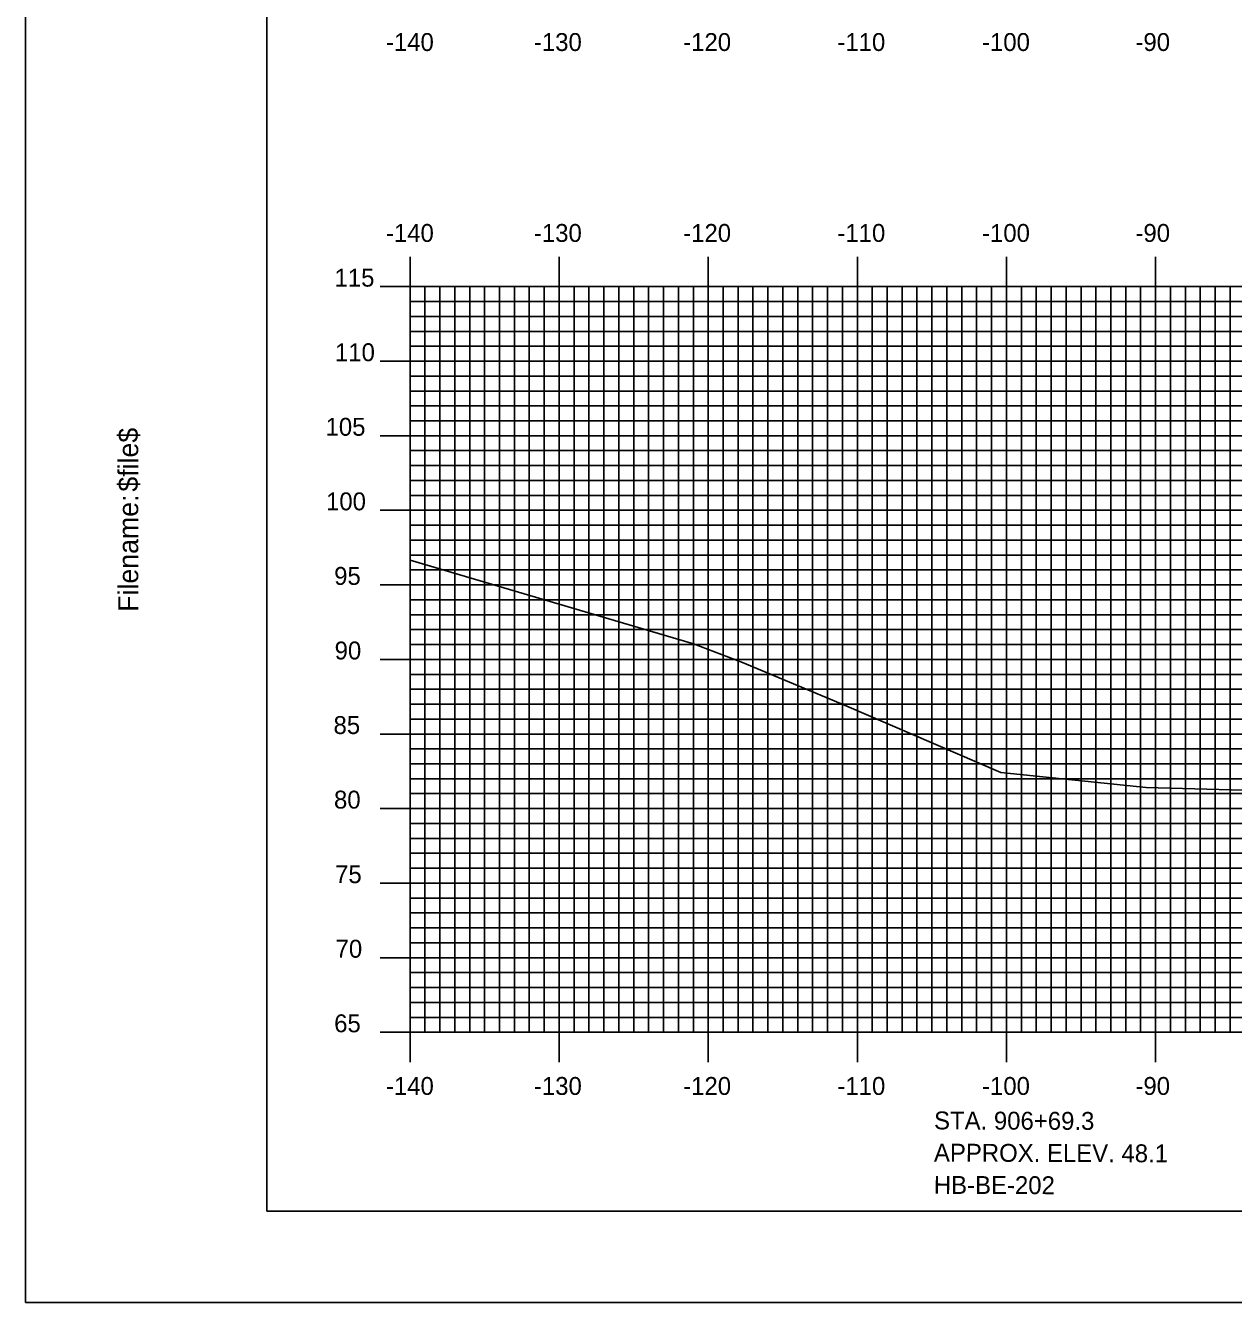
# Model space of a CAD drawing. Extents: x 857897 to 858240, y 364765 to 364985.
# Drawn here: x 857897 to 857978, y 364765.2 to 364850.8 of the extents above; entities that cross this region are included whole.
import ezdxf

# ---------------------------------------------------------------- set-up
doc = ezdxf.new("R2010")
doc.units = 0
for name, color, linetype in [('BORDER', 7, 'Continuous'), ('BORING - REFUSAL', 7, 'Continuous'), ('H_V ANNOTATION', 7, 'Continuous'), ('MAJOR', 7, 'Continuous'), ('MINOR', 7, 'Continuous'), ('PLOT BOUNDARY', 7, 'Continuous'), ('S_Roadway_Centerline', 7, 'Continuous')]:
    doc.layers.add(name, color=color, linetype=linetype)

msp = doc.modelspace()

# ---------------------------------------------------------------- linework, layer by layer
at = {"layer": 'BORDER'}
msp.add_lwpolyline([(857913.221, 364771.302), (858233.221, 364771.302), (858233.221, 364981.302), (857913.221, 364981.302)], close=True, dxfattribs=at)
at = {"layer": 'MAJOR'}
for p, q in [((857922.821, 364835.306), (857922.821, 364833.302)), ((857932.821, 364835.306), (857932.821, 364833.302)), ((857942.821, 364835.306), (857942.821, 364833.302)), ((857952.821, 364835.306), (857952.821, 364833.302)), ((857962.821, 364835.306), (857962.821, 364833.302)), ((857972.821, 364835.306), (857972.821, 364833.302)), ((857920.817, 364833.302), (857922.821, 364833.302)), ((857922.821, 364833.302), (858202.821, 364833.302)), ((857922.821, 364783.302), (857922.821, 364833.302)), ((857922.821, 364783.302), (857922.821, 364833.302)), ((857922.821, 364833.302), (858202.821, 364833.302)), ((857932.821, 364783.302), (857932.821, 364833.302)), ((857942.821, 364783.302), (857942.821, 364833.302)), ((857952.821, 364783.302), (857952.821, 364833.302)), ((857962.821, 364783.302), (857962.821, 364833.302)), ((857972.821, 364783.302), (857972.821, 364833.302)), ((857920.817, 364828.302), (857922.821, 364828.302)), ((857922.821, 364828.302), (858202.821, 364828.302)), ((857920.817, 364823.302), (857922.821, 364823.302)), ((857922.821, 364823.302), (858202.821, 364823.302)), ((857920.817, 364818.302), (857922.821, 364818.302)), ((857922.821, 364818.302), (858202.821, 364818.302)), ((857920.817, 364813.302), (857922.821, 364813.302)), ((857922.821, 364813.302), (858202.821, 364813.302)), ((857920.817, 364808.302), (857922.821, 364808.302)), ((857922.821, 364808.302), (858202.821, 364808.302)), ((857920.817, 364803.302), (857922.821, 364803.302)), ((857922.821, 364803.302), (858202.821, 364803.302)), ((857920.817, 364798.302), (857922.821, 364798.302)), ((857922.821, 364798.302), (858202.821, 364798.302)), ((857920.817, 364793.302), (857922.821, 364793.302)), ((857922.821, 364793.302), (858202.821, 364793.302)), ((857920.817, 364788.302), (857922.821, 364788.302)), ((857922.821, 364788.302), (858202.821, 364788.302)), ((857920.817, 364783.302), (857922.821, 364783.302)), ((857922.821, 364783.302), (858202.821, 364783.302)), ((857922.821, 364783.302), (858202.821, 364783.302)), ((857922.821, 364781.298), (857922.821, 364783.302)), ((857932.821, 364781.298), (857932.821, 364783.302)), ((857942.821, 364781.298), (857942.821, 364783.302)), ((857952.821, 364781.298), (857952.821, 364783.302)), ((857962.821, 364781.298), (857962.821, 364783.302)), ((857972.821, 364781.298), (857972.821, 364783.302))]:
    msp.add_line(p, q, dxfattribs=at)
at = {"layer": 'MINOR'}
for p, q in [((857923.821, 364783.302), (857923.821, 364833.302)), ((857924.821, 364783.302), (857924.821, 364833.302)), ((857925.821, 364783.302), (857925.821, 364833.302)), ((857926.821, 364783.302), (857926.821, 364833.302)), ((857927.821, 364783.302), (857927.821, 364833.302)), ((857928.821, 364783.302), (857928.821, 364833.302)), ((857929.821, 364783.302), (857929.821, 364833.302)), ((857930.821, 364783.302), (857930.821, 364833.302)), ((857931.821, 364783.302), (857931.821, 364833.302)), ((857933.821, 364783.302), (857933.821, 364833.302)), ((857934.821, 364783.302), (857934.821, 364833.302)), ((857935.821, 364783.302), (857935.821, 364833.302)), ((857936.821, 364783.302), (857936.821, 364833.302)), ((857937.821, 364783.302), (857937.821, 364833.302)), ((857938.821, 364783.302), (857938.821, 364833.302)), ((857939.821, 364783.302), (857939.821, 364833.302)), ((857940.821, 364783.302), (857940.821, 364833.302)), ((857941.821, 364783.302), (857941.821, 364833.302)), ((857943.821, 364783.302), (857943.821, 364833.302)), ((857944.821, 364783.302), (857944.821, 364833.302)), ((857945.821, 364783.302), (857945.821, 364833.302)), ((857946.821, 364783.302), (857946.821, 364833.302)), ((857947.821, 364783.302), (857947.821, 364833.302)), ((857948.821, 364783.302), (857948.821, 364833.302)), ((857949.821, 364783.302), (857949.821, 364833.302)), ((857950.821, 364783.302), (857950.821, 364833.302)), ((857951.821, 364783.302), (857951.821, 364833.302)), ((857953.821, 364783.302), (857953.821, 364833.302)), ((857954.821, 364783.302), (857954.821, 364833.302)), ((857955.821, 364783.302), (857955.821, 364833.302)), ((857956.821, 364783.302), (857956.821, 364833.302)), ((857957.821, 364783.302), (857957.821, 364833.302)), ((857958.821, 364783.302), (857958.821, 364833.302)), ((857959.821, 364783.302), (857959.821, 364833.302)), ((857960.821, 364783.302), (857960.821, 364833.302)), ((857961.821, 364783.302), (857961.821, 364833.302)), ((857963.821, 364783.302), (857963.821, 364833.302)), ((857964.821, 364783.302), (857964.821, 364833.302)), ((857965.821, 364783.302), (857965.821, 364833.302)), ((857966.821, 364783.302), (857966.821, 364833.302)), ((857967.821, 364783.302), (857967.821, 364833.302)), ((857968.821, 364783.302), (857968.821, 364833.302)), ((857969.821, 364783.302), (857969.821, 364833.302)), ((857970.821, 364783.302), (857970.821, 364833.302)), ((857971.821, 364783.302), (857971.821, 364833.302)), ((857973.821, 364783.302), (857973.821, 364833.302)), ((857974.821, 364783.302), (857974.821, 364833.302)), ((857975.821, 364783.302), (857975.821, 364833.302)), ((857976.821, 364783.302), (857976.821, 364833.302)), ((857977.821, 364783.302), (857977.821, 364833.302)), ((857922.821, 364832.302), (858202.821, 364832.302)), ((857922.821, 364832.302), (857924.825, 364832.302)), ((857922.821, 364831.302), (858202.821, 364831.302)), ((857922.821, 364831.302), (857924.825, 364831.302)), ((857922.821, 364830.302), (858202.821, 364830.302)), ((857922.821, 364830.302), (857924.825, 364830.302)), ((857922.821, 364829.302), (858202.821, 364829.302)), ((857922.821, 364829.302), (857924.825, 364829.302)), ((857922.821, 364827.302), (858202.821, 364827.302)), ((857922.821, 364827.302), (857924.825, 364827.302)), ((857922.821, 364826.302), (858202.821, 364826.302)), ((857922.821, 364826.302), (857924.825, 364826.302)), ((857922.821, 364825.302), (858202.821, 364825.302)), ((857922.821, 364825.302), (857924.825, 364825.302)), ((857922.821, 364824.302), (858202.821, 364824.302)), ((857922.821, 364824.302), (857924.825, 364824.302)), ((857922.821, 364822.302), (858202.821, 364822.302)), ((857922.821, 364822.302), (857924.825, 364822.302)), ((857922.821, 364821.302), (858202.821, 364821.302)), ((857922.821, 364821.302), (857924.825, 364821.302)), ((857922.821, 364820.302), (858202.821, 364820.302)), ((857922.821, 364820.302), (857924.825, 364820.302)), ((857922.821, 364819.302), (858202.821, 364819.302)), ((857922.821, 364819.302), (857924.825, 364819.302)), ((857922.821, 364817.302), (858202.821, 364817.302)), ((857922.821, 364817.302), (857924.825, 364817.302)), ((857922.821, 364816.302), (858202.821, 364816.302)), ((857922.821, 364816.302), (857924.825, 364816.302)), ((857922.821, 364815.302), (858202.821, 364815.302)), ((857922.821, 364815.302), (857924.825, 364815.302)), ((857922.821, 364814.302), (858202.821, 364814.302)), ((857922.821, 364814.302), (857924.825, 364814.302)), ((857922.821, 364812.302), (858202.821, 364812.302)), ((857922.821, 364812.302), (857924.825, 364812.302)), ((857922.821, 364811.302), (858202.821, 364811.302)), ((857922.821, 364811.302), (857924.825, 364811.302)), ((857922.821, 364810.302), (858202.821, 364810.302)), ((857922.821, 364810.302), (857924.825, 364810.302)), ((857922.821, 364809.302), (858202.821, 364809.302)), ((857922.821, 364809.302), (857924.825, 364809.302)), ((857922.821, 364807.302), (858202.821, 364807.302)), ((857922.821, 364807.302), (857924.825, 364807.302)), ((857922.821, 364806.302), (858202.821, 364806.302)), ((857922.821, 364806.302), (857924.825, 364806.302)), ((857922.821, 364805.302), (858202.821, 364805.302)), ((857922.821, 364805.302), (857924.825, 364805.302)), ((857922.821, 364804.302), (858202.821, 364804.302)), ((857922.821, 364804.302), (857924.825, 364804.302)), ((857922.821, 364802.302), (858202.821, 364802.302)), ((857922.821, 364802.302), (857924.825, 364802.302)), ((857922.821, 364801.302), (858202.821, 364801.302)), ((857922.821, 364801.302), (857924.825, 364801.302)), ((857922.821, 364800.302), (858202.821, 364800.302)), ((857922.821, 364800.302), (857924.825, 364800.302)), ((857922.821, 364799.302), (858202.821, 364799.302)), ((857922.821, 364799.302), (857924.825, 364799.302)), ((857922.821, 364797.302), (858202.821, 364797.302)), ((857922.821, 364797.302), (857924.825, 364797.302)), ((857922.821, 364796.302), (858202.821, 364796.302)), ((857922.821, 364796.302), (857924.825, 364796.302)), ((857922.821, 364795.302), (858202.821, 364795.302)), ((857922.821, 364795.302), (857924.825, 364795.302)), ((857922.821, 364794.302), (858202.821, 364794.302)), ((857922.821, 364794.302), (857924.825, 364794.302)), ((857922.821, 364792.302), (858202.821, 364792.302)), ((857922.821, 364792.302), (857924.825, 364792.302)), ((857922.821, 364791.302), (858202.821, 364791.302)), ((857922.821, 364791.302), (857924.825, 364791.302)), ((857922.821, 364790.302), (858202.821, 364790.302)), ((857922.821, 364790.302), (857924.825, 364790.302)), ((857922.821, 364789.302), (858202.821, 364789.302)), ((857922.821, 364789.302), (857924.825, 364789.302)), ((857922.821, 364787.302), (858202.821, 364787.302)), ((857922.821, 364787.302), (857924.825, 364787.302)), ((857922.821, 364786.302), (858202.821, 364786.302)), ((857922.821, 364786.302), (857924.825, 364786.302)), ((857922.821, 364785.302), (858202.821, 364785.302)), ((857922.821, 364785.302), (857924.825, 364785.302)), ((857922.821, 364784.302), (858202.821, 364784.302)), ((857922.821, 364784.302), (857924.825, 364784.302))]:
    msp.add_line(p, q, dxfattribs=at)
at = {"layer": 'PLOT BOUNDARY'}
msp.add_lwpolyline([(857897.034, 364765.184), (858237.034, 364765.184), (858237.034, 364985.184), (857897.034, 364985.184)], close=True, dxfattribs=at)
at = {"layer": 'S_Roadway_Centerline'}
msp.add_lwpolyline([(857922.821, 364814.97), (857941.825, 364809.359), (857945.12, 364808.108), (857951.954, 364805.245), (857962.433, 364800.714), (857972.196, 364799.708), (857991.726, 364799.171), (857996.315, 364799.061), (858003.846, 364798.865), (858013.027, 364798.718), (858019.735, 364798.597), (858026.217, 364798.531), (858028.554, 364798.624), (858052.488, 364799.533), (858057.96, 364799.363), (858073.459, 364798.606), (858081.082, 364798.117)], dxfattribs=at)

# ---------------------------------------------------------------- texts
at = {"layer": 'BORDER'}
for s, p in [('$file$', (857904.591, 364819.553)), ('Filename:', (857904.591, 364811.499))]:
    msp.add_text(s, height=1.3392, rotation=90, dxfattribs=at).set_placement(p)
at = {"layer": 'BORING - REFUSAL'}
for s, p in [('STA. 906+69.3', (857957.964, 364776.79)), ('APPROX. ELEV. 48.1', (857957.957, 364774.63)), ('HB-BE-202', (857957.95, 364772.47))]:
    msp.add_text(s, height=1.2, rotation=359.81416, dxfattribs=at).set_placement(p)
at = {"layer": 'H_V ANNOTATION'}
for s, p in [('-140', (857921.205, 364849.102)), ('-130', (857931.13, 364849.102)), ('-120', (857941.14, 364849.102)), ('-110', (857951.483, 364849.102)), ('-100', (857961.183, 364849.102)), ('-90', (857971.472, 364849.102)), ('-140', (857921.205, 364836.302)), ('-130', (857931.13, 364836.302)), ('-120', (857941.14, 364836.302)), ('-110', (857951.483, 364836.302)), ('-100', (857961.183, 364836.302)), ('-90', (857971.472, 364836.302)), ('115', (857917.755, 364833.302)), ('110', (857917.787, 364828.302)), ('105', (857917.155, 364823.302)), ('100', (857917.187, 364818.302)), ('95', (857917.733, 364813.302)), ('90', (857917.765, 364808.302)), ('85', (857917.69, 364803.302)), ('80', (857917.722, 364798.302)), ('75', (857917.797, 364793.302)), ('70', (857917.829, 364788.302)), ('65', (857917.733, 364783.302)), ('-140', (857921.205, 364779.102)), ('-130', (857931.13, 364779.102)), ('-120', (857941.14, 364779.102)), ('-110', (857951.483, 364779.102)), ('-100', (857961.183, 364779.102)), ('-90', (857971.472, 364779.102))]:
    msp.add_text(s, height=1.2, dxfattribs=at).set_placement(p)
at = {"layer": 'MAJOR'}
msp.add_text('-', height=0.012, dxfattribs=at).set_placement((857922.812, 364783.302))

doc.saveas('drawing.dxf')
